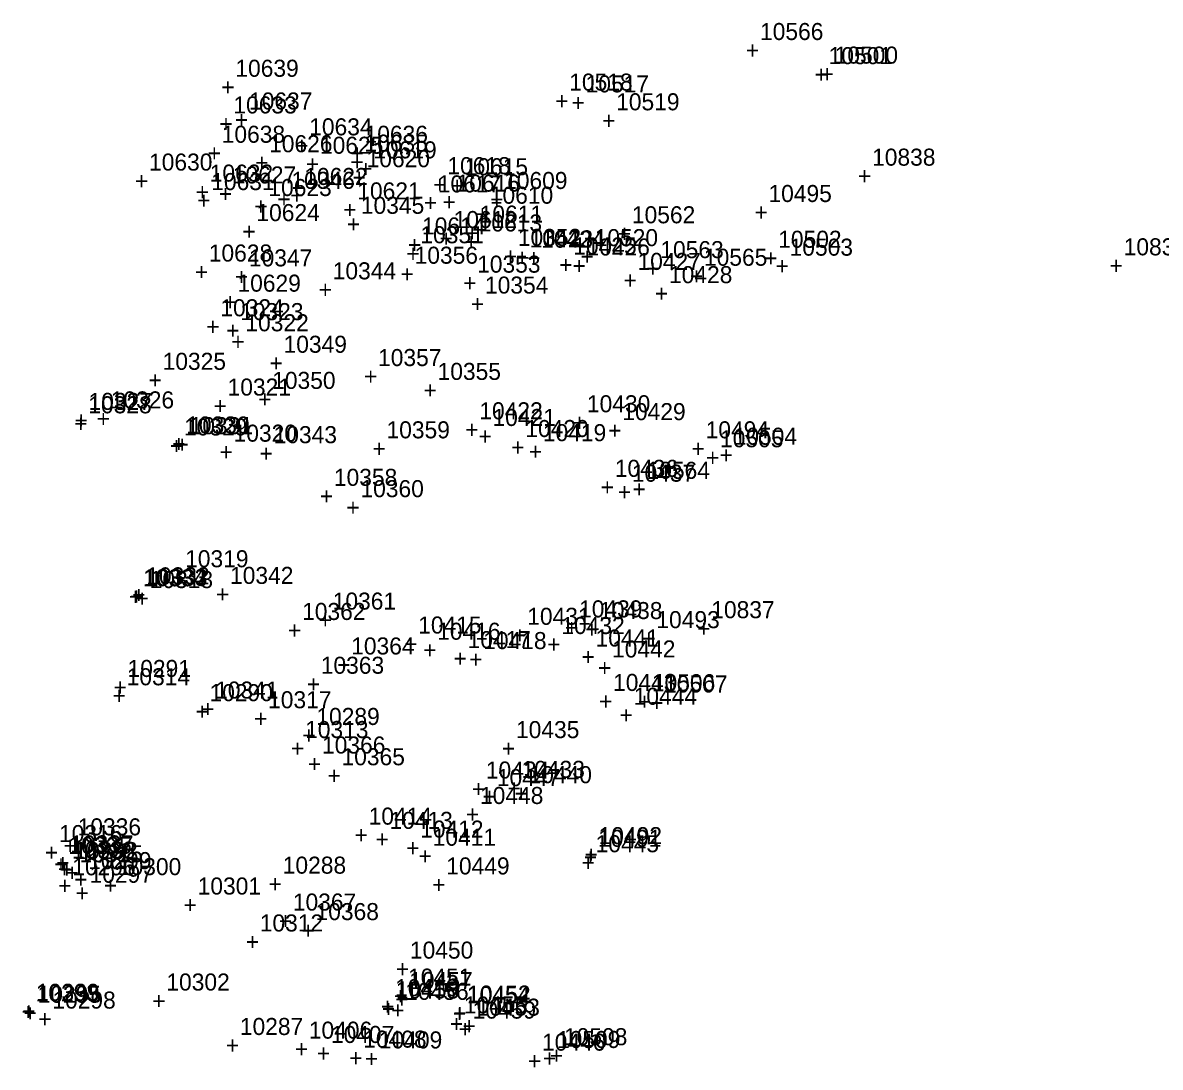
# Model space of a CAD drawing. Extents: x 1136220 to 1137808, y 528804 to 531215.
# Drawn here: x 1136920.2 to 1137087, y 530227.9 to 530381.1 of the extents above; entities that cross this region are included whole.
import ezdxf

# ---------------------------------------------------------------- set-up
doc = ezdxf.new("R2010")
doc.units = 0
for name, color, linetype in [('S_Buildings', 7, 'Continuous'), ('S_Buildings_Attachments', 7, 'Continuous'), ('S_Buildings_Steps_Brick', 7, 'Continuous'), ('S_Curb_Type_3', 7, 'Continuous'), ('S_Drainage_CB', 7, 'Continuous'), ('S_Fencing_ChainLink', 7, 'Continuous'), ('S_Fencing_Page', 7, 'Continuous'), ('S_Ground_Elevation', 7, 'Continuous'), ('S_Property_Garden', 7, 'Continuous'), ('S_Property_Light', 7, 'Continuous'), ('S_Railroad_Tracks', 7, 'Continuous'), ('S_RetWall_Top', 7, 'Continuous'), ('S_Roadway_Drive_Paved', 7, 'Continuous'), ('S_Roadway_Sidewalks', 7, 'Continuous'), ('S_Traffic_Post_Conc', 7, 'Continuous'), ('S_Trees_Bush', 7, 'Continuous'), ('S_Utilities_Pole_Power', 7, 'Continuous')]:
    doc.layers.add(name, color=color, linetype=linetype)

msp = doc.modelspace()

# ---------------------------------------------------------------- texts
at = {"layer": 'S_Buildings'}
for s, p in [('10838', (1137044.78, 530360.11)), ('+', (1137042.71, 530357.36)), ('10839', (1137081.68, 530346.96)), ('+', (1137079.62, 530344.21)), ('10837', (1137021.19, 530293.74)), ('+', (1137019.13, 530290.99))]:
    msp.add_text(s, height=2.5, dxfattribs=at).set_placement(p)
at = {"layer": 'S_Buildings_Attachments'}
for s, p in [('10458', (1136974.92, 530237.96)), ('+', (1136972.86, 530235.21)), ('10459', (1136986.19, 530235.01)), ('+', (1136984.13, 530232.26))]:
    msp.add_text(s, height=2.5, dxfattribs=at).set_placement(p)
at = {"layer": 'S_Buildings_Steps_Brick'}
for s, p in [('10457', (1136976.9, 530239.35)), ('10456', (1136976.3, 530237.76)), ('10454', (1136985.34, 530237.25)), ('+', (1136974.84, 530236.6)), ('10455', (1136984.91, 530235.77)), ('+', (1136974.24, 530235.01)), ('+', (1136983.28, 530234.5)), ('+', (1136982.85, 530233.02))]:
    msp.add_text(s, height=2.5, dxfattribs=at).set_placement(p)
at = {"layer": 'S_Curb_Type_3'}
for s, p in [('10327', (1136929.86, 530324.29)), ('+', (1136927.8, 530321.54)), ('10330', (1136944.18, 530320.83)), ('+', (1136942.11, 530318.08)), ('10333', (1136937.99, 530298.47)), ('+', (1136935.93, 530295.72)), ('10336', (1136928.26, 530261.89)), ('+', (1136926.2, 530259.14)), ('10337', (1136927.17, 530259.39)), ('+', (1136925.11, 530256.64))]:
    msp.add_text(s, height=2.5, dxfattribs=at).set_placement(p)
at = {"layer": 'S_Drainage_CB'}
for s, p in [('10316', (1136925.52, 530260.9)), ('+', (1136923.46, 530258.15))]:
    msp.add_text(s, height=2.5, dxfattribs=at).set_placement(p)
at = {"layer": 'S_Fencing_ChainLink'}
for s, p in [('10495', (1137029.58, 530354.78)), ('+', (1137027.52, 530352.03)), ('10494', (1137020.37, 530320.12)), ('+', (1137018.3, 530317.37)), ('10493', (1137013.14, 530292.28)), ('+', (1137011.08, 530289.53)), ('10491', (1137004.58, 530260.21)), ('+', (1137002.52, 530257.46))]:
    msp.add_text(s, height=2.5, dxfattribs=at).set_placement(p)
at = {"layer": 'S_Fencing_Page'}
for s, p in [('10292', (1136927.77, 530258.4)), ('+', (1136925.71, 530255.65)), ('10293', (1136922.1, 530237.54)), ('+', (1136920.04, 530234.79))]:
    msp.add_text(s, height=2.5, dxfattribs=at).set_placement(p)
at = {"layer": 'S_Ground_Elevation'}
for s, p in [('10566', (1137028.34, 530378.54)), ('+', (1137026.28, 530375.79)), ('10500', (1137039.29, 530375.08)), ('+', (1137037.23, 530372.33)), ('10518', (1137000.36, 530371.12)), ('10637', (1136953.39, 530368.35)), ('+', (1136998.3, 530368.37)), ('+', (1136951.33, 530365.6)), ('10636', (1136970.34, 530363.47)), ('+', (1136968.28, 530360.72)), ('10619', (1136971.62, 530361.18)), ('10618', (1136982.48, 530358.86)), ('10346', (1136959.61, 530356.71)), ('+', (1136969.56, 530358.43)), ('10609', (1136990.81, 530356.69)), ('+', (1136980.42, 530356.11)), ('+', (1136957.55, 530353.96)), ('10345', (1136969.8, 530353.05)), ('+', (1136988.75, 530353.94)), ('10562', (1137009.55, 530351.66)), ('+', (1136967.74, 530350.3)), ('10614', (1136978.77, 530350.02)), ('10613', (1136987.08, 530350.46)), ('10352', (1136992.82, 530348.34)), ('10423', (1136994.56, 530348.13)), ('10520', (1137004.09, 530348.31)), ('+', (1137007.49, 530348.91)), ('+', (1136976.71, 530347.27)), ('+', (1136985.02, 530347.71)), ('10426', (1137002.89, 530346.94)), ('10563', (1137013.72, 530346.55)), ('10503', (1137032.68, 530346.91)), ('10347', (1136953.38, 530345.34)), ('10356', (1136977.68, 530345.73)), ('+', (1136990.76, 530345.59)), ('+', (1136992.5, 530345.38)), ('+', (1137002.03, 530345.56)), ('10427', (1137010.37, 530344.82)), ('10565', (1137020.12, 530345.43)), ('10344', (1136965.67, 530343.44)), ('10353', (1136986.85, 530344.42)), ('+', (1137000.83, 530344.19)), ('+', (1137011.66, 530343.8)), ('+', (1137030.61, 530344.16)), ('+', (1136951.32, 530342.59)), ('+', (1136975.62, 530342.98)), ('10354', (1136988, 530341.35)), ('+', (1137008.31, 530342.07)), ('10428', (1137014.99, 530342.88)), ('+', (1137018.06, 530342.68)), ('+', (1136963.61, 530340.69)), ('+', (1136984.79, 530341.67)), ('+', (1137012.93, 530340.13)), ('+', (1136985.94, 530338.6)), ('10357', (1136972.32, 530330.72)), ('10355', (1136981.05, 530328.69)), ('+', (1136970.26, 530327.97)), ('+', (1136978.99, 530325.94)), ('10430', (1137002.95, 530323.94)), ('10422', (1136987.17, 530322.91)), ('10429', (1137008.14, 530322.79)), ('10359', (1136973.56, 530320.12)), ('+', (1136985.11, 530320.16)), ('10419', (1136996.49, 530319.7)), ('+', (1137000.89, 530321.19)), ('10343', (1136957, 530319.41)), ('+', (1137006.08, 530320.04)), ('10504', (1137024.48, 530319.18)), ('+', (1136971.5, 530317.37)), ('+', (1136994.43, 530316.95)), ('+', (1136954.94, 530316.66)), ('+', (1137022.42, 530316.43)), ('10358', (1136965.84, 530313.15)), ('10564', (1137011.7, 530314.18)), ('10360', (1136969.74, 530311.49)), ('+', (1136963.78, 530310.4)), ('+', (1137009.64, 530311.43)), ('+', (1136967.67, 530308.74)), ('10318', (1136938.82, 530298.16)), ('10342', (1136950.61, 530298.77)), ('+', (1136936.76, 530295.41)), ('+', (1136948.55, 530296.02)), ('10361', (1136965.67, 530295)), ('10362', (1136961.18, 530293.48)), ('+', (1136963.61, 530292.25)), ('10415', (1136978.21, 530291.49)), ('10431', (1136994.2, 530292.77)), ('10432', (1136999.2, 530291.42)), ('+', (1136959.11, 530290.73)), ('10364', (1136968.38, 530288.42)), ('+', (1136976.15, 530288.74)), ('10418', (1136987.74, 530289.21)), ('+', (1136992.13, 530290.02)), ('+', (1136997.14, 530288.67)), ('10291', (1136935.58, 530285.12)), ('10363', (1136963.92, 530285.59)), ('+', (1136966.32, 530285.67)), ('+', (1136985.68, 530286.46)), ('+', (1136933.52, 530282.37)), ('10290', (1136947.6, 530281.57)), ('10341', (1136948.42, 530281.95)), ('+', (1136961.86, 530282.84)), ('10507', (1137014.28, 530282.84)), ('+', (1137012.22, 530280.09)), ('+', (1136945.54, 530278.82)), ('+', (1136946.36, 530279.2)), ('10289', (1136963.27, 530278.08)), ('+', (1136961.21, 530275.33)), ('10366', (1136964.1, 530273.89)), ('10365', (1136966.96, 530272.17)), ('+', (1136962.04, 530271.14)), ('10434', (1136988.13, 530270.22)), ('10433', (1136993.36, 530270.32)), ('+', (1136964.9, 530269.42)), ('+', (1136986.07, 530267.47)), ('+', (1136991.29, 530267.57)), ('10414', (1136970.94, 530263.46)), ('+', (1136968.88, 530260.71)), ('10411', (1136980.33, 530260.37)), ('10492', (1137004.67, 530260.6)), ('10288', (1136958.34, 530256.27)), ('+', (1136978.27, 530257.62)), ('+', (1137002.61, 530257.85)), ('+', (1136956.27, 530253.52)), ('10367', (1136959.82, 530250.86)), ('10368', (1136963.15, 530249.46)), ('+', (1136957.76, 530248.11)), ('+', (1136961.09, 530246.71)), ('10410', (1136974.81, 530238.3)), ('+', (1136972.75, 530235.55)), ('10287', (1136952.05, 530232.61)), ('10406', (1136962.16, 530232.07)), ('10409', (1136972.44, 530230.64)), ('10508', (1136999.59, 530231.11)), ('+', (1136949.99, 530229.86)), ('+', (1136960.1, 530229.32)), ('+', (1136997.53, 530228.36)), ('+', (1136970.38, 530227.89))]:
    msp.add_text(s, height=2.5, dxfattribs=at).set_placement(p)
at = {"layer": 'S_Property_Garden'}
for s, p in [('10324', (1136949.19, 530338.02)), ('10323', (1136952.09, 530337.46)), ('+', (1136947.13, 530335.27)), ('10322', (1136952.86, 530335.82)), ('+', (1136950.03, 530334.71)), ('+', (1136950.8, 530333.07)), ('10325', (1136940.72, 530330.17)), ('+', (1136938.66, 530327.42)), ('10321', (1136950.25, 530326.39)), ('10326', (1136933.11, 530324.51)), ('+', (1136948.19, 530323.64)), ('+', (1136931.05, 530321.76)), ('10331', (1136944.68, 530320.73)), ('10320', (1136951.13, 530319.63)), ('+', (1136942.62, 530317.98)), ('+', (1136949.07, 530316.88)), ('10319', (1136944.02, 530301.21)), ('10332', (1136938.32, 530298.7)), ('+', (1136941.96, 530298.46)), ('+', (1136936.26, 530295.95)), ('10314', (1136935.45, 530283.9)), ('+', (1136933.39, 530281.15)), ('10313', (1136961.62, 530276.16)), ('+', (1136959.55, 530273.41)), ('10315', (1136928.52, 530257.94)), ('10299', (1136929.8, 530256.94)), ('+', (1136926.46, 530255.19)), ('10296', (1136927.47, 530256.03)), ('10297', (1136930.01, 530254.94)), ('10300', (1136934.16, 530256.06)), ('+', (1136927.74, 530254.19)), ('10301', (1136945.86, 530253.21)), ('+', (1136925.41, 530253.28)), ('+', (1136927.95, 530252.19)), ('+', (1136932.1, 530253.31)), ('+', (1136943.79, 530250.46)), ('10312', (1136954.97, 530247.79)), ('+', (1136952.91, 530245.04)), ('10302', (1136941.27, 530239.13)), ('10295', (1136922.39, 530237.34)), ('10298', (1136924.55, 530236.48)), ('+', (1136939.21, 530236.38)), ('+', (1136920.33, 530234.59)), ('+', (1136922.49, 530233.73))]:
    msp.add_text(s, height=2.5, dxfattribs=at).set_placement(p)
at = {"layer": 'S_Property_Light'}
for s, p in [('10632', (1136947.63, 530357.77)), ('+', (1136945.57, 530355.02)), ('10351', (1136978.53, 530348.73)), ('+', (1136976.47, 530345.98))]:
    msp.add_text(s, height=2.5, dxfattribs=at).set_placement(p)
at = {"layer": 'S_Railroad_Tracks'}
for s, p in [('10517', (1137002.76, 530370.86)), ('10519', (1137007.24, 530368.23)), ('+', (1137000.7, 530368.11)), ('+', (1137005.18, 530365.48)), ('10424', (1136996.24, 530348.08)), ('10425', (1137000.95, 530347.08)), ('+', (1136994.18, 530345.33)), ('+', (1136998.89, 530344.33)), ('10421', (1136989.1, 530321.93)), ('10420', (1136993.92, 530320.31)), ('+', (1136987.04, 530319.18)), ('+', (1136991.86, 530317.56)), ('10416', (1136980.99, 530290.58)), ('10417', (1136985.45, 530289.35)), ('+', (1136978.93, 530287.83)), ('+', (1136983.39, 530286.6)), ('10413', (1136973.99, 530262.84)), ('10412', (1136978.49, 530261.56)), ('+', (1136971.93, 530260.09)), ('+', (1136976.43, 530258.81)), ('10407', (1136965.41, 530231.44)), ('10408', (1136970.14, 530230.75)), ('+', (1136963.35, 530228.69)), ('+', (1136968.08, 530228))]:
    msp.add_text(s, height=2.5, dxfattribs=at).set_placement(p)
at = {"layer": 'S_RetWall_Top'}
for s, p in [('10501', (1137038.4, 530375)), ('+', (1137036.34, 530372.25)), ('10633', (1136951.1, 530367.77)), ('+', (1136949.04, 530365.02)), ('10634', (1136962.22, 530364.56)), ('10635', (1136970.32, 530362.17)), ('+', (1136960.16, 530361.81)), ('10630', (1136938.73, 530359.39)), ('+', (1136968.26, 530359.42)), ('10631', (1136947.85, 530356.53)), ('+', (1136936.67, 530356.64)), ('+', (1136945.79, 530353.78)), ('10502', (1137031.01, 530348.07)), ('+', (1137028.95, 530345.32)), ('10505', (1137022.48, 530318.81)), ('+', (1137020.42, 530316.06)), ('10506', (1137012.48, 530283.03)), ('+', (1137010.41, 530280.28)), ('10509', (1136998.56, 530230.7)), ('+', (1136996.5, 530227.95))]:
    msp.add_text(s, height=2.5, dxfattribs=at).set_placement(p)
at = {"layer": 'S_Roadway_Drive_Paved'}
for s, p in [('10639', (1136951.39, 530373.15)), ('+', (1136949.33, 530370.4)), ('10638', (1136949.39, 530363.47)), ('+', (1136947.33, 530360.72)), ('10328', (1136929.82, 530323.79)), ('+', (1136927.76, 530321.04)), ('10329', (1136943.86, 530320.54)), ('+', (1136941.8, 530317.79)), ('10436', (1137007.04, 530314.47)), ('10437', (1137009.54, 530313.76)), ('+', (1137004.97, 530311.72)), ('+', (1137007.48, 530311.01)), ('10334', (1136937.85, 530298.42)), ('+', (1136935.79, 530295.67)), ('10439', (1137001.8, 530293.86)), ('10438', (1137004.74, 530293.61)), ('+', (1136999.74, 530291.11)), ('+', (1137002.68, 530290.86)), ('10441', (1137004.22, 530289.59)), ('10442', (1137006.64, 530287.98)), ('+', (1137002.16, 530286.84)), ('+', (1137004.58, 530285.23)), ('10443', (1137006.79, 530283.07)), ('+', (1137004.73, 530280.32)), ('10444', (1137009.81, 530281.05)), ('+', (1137007.75, 530278.3)), ('10447', (1136989.74, 530269.11)), ('10440', (1136994.39, 530269.54)), ('10448', (1136987.27, 530266.49)), ('+', (1136992.33, 530266.79)), ('+', (1136987.67, 530266.36)), ('+', (1136985.2, 530263.74)), ('10335', (1136926.9, 530259.18)), ('10338', (1136927.43, 530258.48)), ('10445', (1137004.23, 530259.41)), ('+', (1136924.84, 530256.43)), ('+', (1136925.37, 530255.73)), ('10449', (1136982.32, 530256.16)), ('+', (1137002.17, 530256.66)), ('+', (1136980.26, 530253.41)), ('10450', (1136976.99, 530243.81)), ('+', (1136974.93, 530241.06)), ('10451', (1136976.71, 530239.85)), ('10339', (1136922.17, 530237.62)), ('+', (1136974.65, 530237.1)), ('10452', (1136985.4, 530237.36)), ('10453', (1136986.76, 530235.44)), ('+', (1136920.11, 530234.87)), ('+', (1136983.34, 530234.61)), ('+', (1136984.7, 530232.69)), ('10446', (1136996.37, 530230.31)), ('+', (1136994.31, 530227.56))]:
    msp.add_text(s, height=2.5, dxfattribs=at).set_placement(p)
at = {"layer": 'S_Roadway_Sidewalks'}
for s, p in [('10626', (1136956.34, 530362.08)), ('10625', (1136963.8, 530361.86)), ('10620', (1136970.64, 530359.89)), ('+', (1136954.28, 530359.33)), ('+', (1136961.73, 530359.11)), ('10615', (1136985.02, 530358.71)), ('10627', (1136951.02, 530357.5)), ('10622', (1136961.5, 530357.28)), ('+', (1136968.58, 530357.14)), ('10623', (1136956.23, 530355.66)), ('10621', (1136969.27, 530355.16)), ('10617', (1136981.08, 530356.19)), ('+', (1136982.96, 530355.96)), ('10616', (1136983.83, 530356.3)), ('+', (1136948.96, 530354.75)), ('+', (1136959.44, 530354.53)), ('+', (1136981.77, 530353.55)), ('10610', (1136988.71, 530354.53)), ('+', (1136954.17, 530352.91)), ('10624', (1136954.48, 530351.98)), ('+', (1136967.21, 530352.41)), ('+', (1136979.02, 530353.44)), ('10611', (1136987.22, 530351.76)), ('10612', (1136983.4, 530350.96)), ('+', (1136986.64, 530351.78)), ('+', (1136952.42, 530349.23)), ('+', (1136985.16, 530349.01)), ('+', (1136981.33, 530348.21)), ('10628', (1136947.49, 530346.05)), ('+', (1136945.43, 530343.3)), ('10629', (1136951.7, 530341.63)), ('+', (1136949.64, 530338.88))]:
    msp.add_text(s, height=2.5, dxfattribs=at).set_placement(p)
at = {"layer": 'S_Traffic_Post_Conc'}
for s, p in [('10435', (1136992.55, 530276.15)), ('+', (1136990.49, 530273.4))]:
    msp.add_text(s, height=2.5, dxfattribs=at).set_placement(p)
at = {"layer": 'S_Trees_Bush'}
for s, p in [('10349', (1136958.46, 530332.67)), ('+', (1136956.4, 530329.92)), ('10350', (1136956.79, 530327.37)), ('+', (1136954.73, 530324.62))]:
    msp.add_text(s, height=2.5, dxfattribs=at).set_placement(p)
at = {"layer": 'S_Utilities_Pole_Power'}
for s, p in [('10317', (1136956.19, 530280.53)), ('+', (1136954.13, 530277.78))]:
    msp.add_text(s, height=2.5, dxfattribs=at).set_placement(p)

doc.saveas('drawing.dxf')
